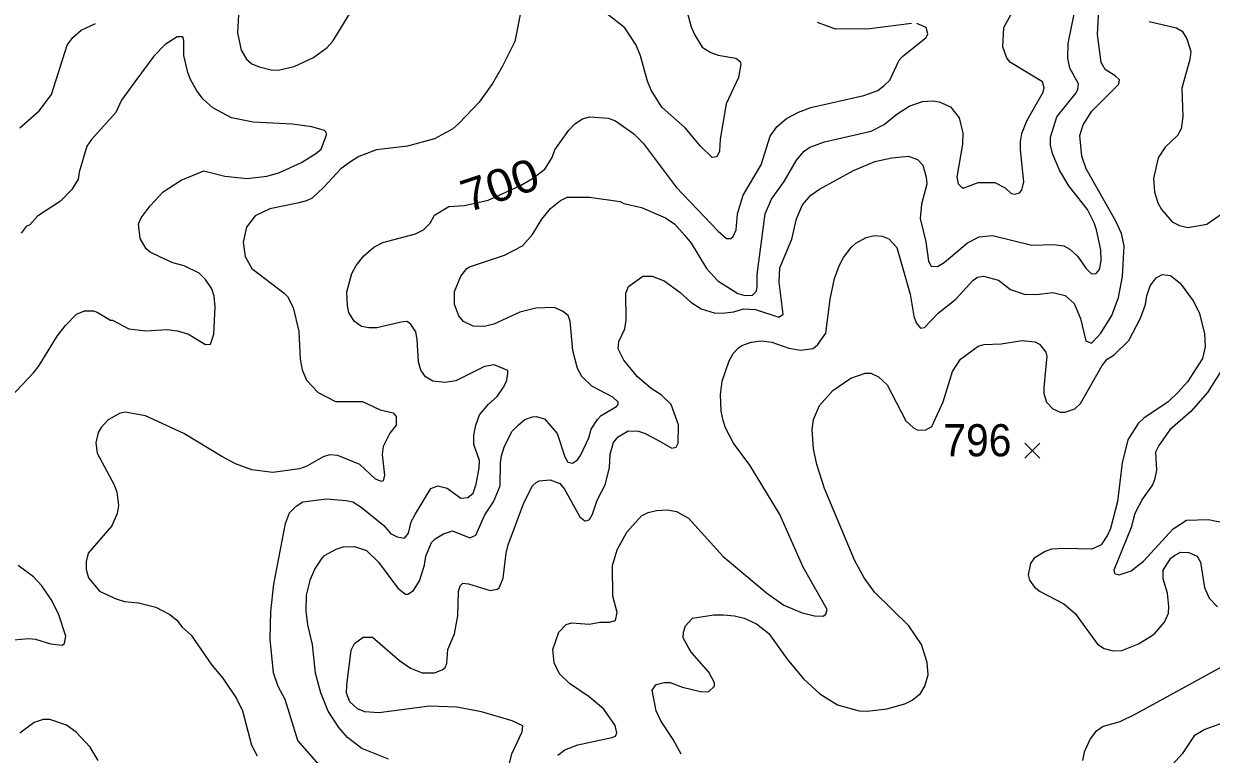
# Model space of a CAD drawing. Extents: x 294.2 to 320.3, y 7482.7 to 7510.7.
# Drawn here: x 304.291 to 307.247, y 7501.322 to 7503.14 of the extents above; entities that cross this region are included whole.
import ezdxf
from ezdxf.enums import TextEntityAlignment as Align

# ---------------------------------------------------------------- set-up
doc = ezdxf.new("R2010")
doc.units = 0
doc.header["$LTSCALE"] = 0.032
for name, color, linetype, lineweight in [('1', 7, 'Continuous', 25), ('2', 7, 'Continuous', 13), ('21', 7, 'Continuous', 25)]:
    doc.layers.add(name, color=color, linetype=linetype, lineweight=lineweight)
doc.layers.add('61', color=7, linetype='Continuous')

msp = doc.modelspace()

# ---------------------------------------------------------------- linework, layer by layer
at = {"layer": '1'}
for points in [[(305.1008, 7502.4213), (305.0969, 7502.4379), (305.0957, 7502.4724), (305.1083, 7502.5186), (305.1189, 7502.5383), (305.1377, 7502.5619), (305.1629, 7502.5839), (305.1849, 7502.5957), (305.2662, 7502.6169), (305.2866, 7502.6271), (305.3031, 7502.6436), (305.3136, 7502.6633), (305.3495, 7502.6853), (305.3883, 7502.6877), (305.4473, 7502.701), (305.5273, 7502.7372), (305.5572, 7502.7551), (305.5878, 7502.7779), (305.6063, 7502.807), (305.6134, 7502.8258), (305.648, 7502.8754), (305.6629, 7502.8911), (305.6818, 7502.9029), (305.6998, 7502.9084), (305.7459, 7502.9052), (305.7639, 7502.8981), (305.8095, 7502.8659), (305.8331, 7502.8423), (305.915, 7502.7332), (306.0195, 7502.6239), (306.0406, 7502.6051), (306.0508, 7502.6058), (306.0566, 7502.6102), (306.0642, 7502.6268), (306.0674, 7502.6664), (306.0821, 7502.713), (306.1262, 7502.7887), (306.149, 7502.8603), (306.1659, 7502.8831), (306.1895, 7502.9043), (306.2193, 7502.9201), (306.25, 7502.9311), (306.3819, 7502.961), (306.4173, 7502.9736), (306.4323, 7502.9862), (306.4464, 7502.9995), (306.47, 7503.0491), (306.4781, 7503.0585), (306.5373, 7503.1056), (306.5412, 7503.115), (306.5373, 7503.1308), (306.5141, 7503.1402)], [(306.5007, 7503.1402), (306.3973, 7503.1268), (306.3116, 7503.126), (306.2664, 7503.1433)], [(305.2448, 7502.3985), (305.2303, 7502.3969), (305.1705, 7502.3828), (305.1501, 7502.3828), (305.132, 7502.3867), (305.1139, 7502.3993), (305.1008, 7502.4213)], [(305.0269, 7501.2959), (304.9738, 7501.3564), (304.9424, 7501.4579), (304.9246, 7501.4904), (304.9131, 7501.5249), (304.9046, 7501.6084), (304.906, 7501.6768), (304.9142, 7501.745), (304.9429, 7501.896), (304.9531, 7501.9228), (304.9696, 7501.9393), (304.9861, 7501.9503), (305.0451, 7501.9574), (305.0942, 7501.9534), (305.1107, 7501.9503), (305.1312, 7501.9369), (305.1874, 7501.8913), (305.2039, 7501.8716), (305.2204, 7501.863), (305.2392, 7501.8599), (305.2487, 7501.8724), (305.2558, 7501.9), (305.266, 7501.9204), (305.3049, 7501.9833), (305.3222, 7501.9896), (305.345, 7501.9841), (305.3788, 7501.9589), (305.3969, 7501.9605), (305.4095, 7501.9715), (305.4173, 7501.9943), (305.4248, 7502.0336), (305.4256, 7502.0533), (305.4114, 7502.0926), (305.4114, 7502.1162), (305.4169, 7502.1413), (305.4258, 7502.1665), (305.4478, 7502.1932), (305.4698, 7502.2121), (305.4855, 7502.2357), (305.4926, 7502.2498), (305.4965, 7502.2687), (305.4958, 7502.2766), (305.4619, 7502.2907), (305.4384, 7502.2868), (305.367, 7502.2515), (305.3395, 7502.2467), (305.3096, 7502.2507), (305.2916, 7502.2609), (305.28, 7502.2774), (305.2737, 7502.2987), (305.2708, 7502.3544), (305.2669, 7502.3733), (305.2543, 7502.393), (305.2448, 7502.3985)]]:
    msp.add_lwpolyline(points, dxfattribs=at)
at = {"layer": '2'}
for points in [[(305.9302, 7503.2155), (305.9523, 7503.132), (305.9609, 7503.113), (305.9798, 7503.0819), (306.001, 7503.068), (306.0195, 7503.0617), (306.0636, 7503.054), (306.0745, 7503.0457), (306.0763, 7503.0393), (306.07, 7503.0061), (306.0393, 7502.9403), (306.0247, 7502.8529), (306.0227, 7502.8228), (306.0163, 7502.8088), (306.0049, 7502.8069), (305.9755, 7502.835), (305.9372, 7502.8809), (305.8803, 7502.9314), (305.8733, 7502.941), (305.8529, 7502.9742), (305.8433, 7502.9972), (305.8261, 7503.0597), (305.8152, 7503.0866), (305.7871, 7503.13), (305.7373, 7503.1689)], [(304.8262, 7503.1619), (304.8236, 7503.1172), (304.8326, 7503.0738), (304.846, 7503.0514), (304.8594, 7503.04), (304.8773, 7503.0329), (304.9073, 7503.0252), (304.9246, 7503.0246), (304.9641, 7503.0336), (305.0127, 7503.0559), (305.0465, 7503.0808), (305.0605, 7503.0967), (305.1161, 7503.1868)], [(305.5305, 7503.1798), (305.5132, 7503.0955), (305.4832, 7503.0342), (305.4577, 7502.9908), (305.4251, 7502.9448), (305.3753, 7502.8924), (305.3594, 7502.8784), (305.3134, 7502.8535), (305.2464, 7502.8356), (305.1697, 7502.826), (305.125, 7502.8094), (305.1046, 7502.796), (305.0803, 7502.7788), (305.0382, 7502.7328), (305.0088, 7502.706), (304.9954, 7502.699), (304.9731, 7502.6932), (304.9041, 7502.6792), (304.8676, 7502.6617), (304.846, 7502.6339), (304.8377, 7502.5962), (304.8428, 7502.5605), (304.8594, 7502.5311), (304.9392, 7502.4691), (304.9475, 7502.4608), (304.9622, 7502.434), (304.9756, 7502.374), (304.9794, 7502.3051), (304.9845, 7502.2783)], [(305.7753, 7502.6972), (305.785, 7502.6922), (305.8286, 7502.6824), (305.8887, 7502.6569), (305.9116, 7502.6415), (305.9365, 7502.6128), (305.9525, 7502.5936), (305.9902, 7502.5304), (306.0189, 7502.5004), (306.0687, 7502.4685), (306.0859, 7502.4634), (306.1051, 7502.464), (306.1146, 7502.4743), (306.1166, 7502.4851), (306.1166, 7502.5158), (306.1364, 7502.6664), (306.1523, 7502.7035), (306.1836, 7502.7475), (306.2143, 7502.8005), (306.2334, 7502.8228), (306.2475, 7502.8324), (306.2845, 7502.8459), (306.4007, 7502.8727), (306.4326, 7502.8893), (306.4639, 7502.9148), (306.4945, 7502.9346), (306.5284, 7502.9467), (306.5527, 7502.948), (306.5699, 7502.9455), (306.5976, 7502.9332), (306.6189, 7502.9059), (306.6286, 7502.8675), (306.628, 7502.8401), (306.6139, 7502.7584), (306.6172, 7502.7411), (306.6267, 7502.7315), (306.6318, 7502.7315), (306.6663, 7502.745), (306.7077, 7502.745), (306.7341, 7502.7316), (306.749, 7502.7177), (306.7582, 7502.716), (306.7691, 7502.7193), (306.7749, 7502.7255), (306.7801, 7502.7466), (306.7723, 7502.8261), (306.7717, 7502.8465), (306.7755, 7502.8669), (306.7876, 7502.8982), (306.8285, 7502.9697), (306.8308, 7502.9806), (306.8263, 7502.9951), (306.7468, 7503.0431), (306.7378, 7503.054), (306.7283, 7503.0827), (306.7308, 7503.1306), (306.7614, 7503.1862)], [(306.0585, 7502.4232), (306.0826, 7502.4307), (306.1125, 7502.4285), (306.1705, 7502.4096), (306.1811, 7502.4174), (306.1715, 7502.4966), (306.1728, 7502.5324), (306.2028, 7502.6039), (306.2149, 7502.6543), (306.2296, 7502.6894), (306.25, 7502.7131), (306.2717, 7502.7284), (306.356, 7502.7749), (306.4096, 7502.7967), (306.4518, 7502.8063), (306.4933, 7502.8101), (306.5156, 7502.8024), (306.529, 7502.7878), (306.5373, 7502.7584), (306.5386, 7502.7405), (306.5258, 7502.6907), (306.522, 7502.655), (306.536, 7502.5975), (306.5431, 7502.549), (306.5495, 7502.5362), (306.5654, 7502.5356), (306.582, 7502.5458), (306.6401, 7502.5943), (306.6689, 7502.6096), (306.7021, 7502.6128), (306.8004, 7502.5885), (306.8541, 7502.5906), (306.8794, 7502.5873), (306.8949, 7502.5789), (306.915, 7502.5606), (306.9345, 7502.5317), (306.9485, 7502.5177), (306.96, 7502.5183), (306.9683, 7502.5285), (306.9728, 7502.5502), (306.9722, 7502.5771), (306.9613, 7502.6269), (306.9555, 7502.6447), (306.9383, 7502.6779), (306.8923, 7502.7366), (306.8693, 7502.7756), (306.8514, 7502.8171), (306.8463, 7502.8376), (306.847, 7502.858), (306.8623, 7502.9078), (306.9102, 7502.9678), (306.9147, 7502.9773), (306.916, 7502.9901), (306.8949, 7503.0291), (306.8898, 7503.0546), (306.8904, 7503.091), (306.9076, 7503.176)], [(306.9721, 7502.3696), (306.9996, 7502.4142), (307.0156, 7502.4583), (307.0258, 7502.5107), (307.0296, 7502.5873), (307.0232, 7502.6179), (307.0092, 7502.6486), (306.9357, 7502.7788), (306.9242, 7502.8107), (306.9198, 7502.8618), (306.9281, 7502.8886), (306.9491, 7502.9225), (307.0168, 7502.9895), (307.0181, 7503.0003), (307.0073, 7503.0099), (306.983, 7503.0259), (306.9728, 7503.0432), (306.9638, 7503.1134), (306.9677, 7503.1894)], [(307.0922, 7503.1453), (307.1605, 7503.1293), (307.1739, 7503.1217), (307.186, 7503.1019), (307.1962, 7503.0712), (307.1937, 7503.0508), (307.1732, 7502.9793), (307.1758, 7502.9078), (307.1714, 7502.8784), (307.1624, 7502.8618), (307.1318, 7502.8324), (307.1145, 7502.8062), (307.103, 7502.7546), (307.1056, 7502.7214), (307.1139, 7502.6945), (307.1228, 7502.6779), (307.1496, 7502.6466), (307.1675, 7502.6377), (307.1886, 7502.6332), (307.2358, 7502.6409), (307.2735, 7502.6677)], [(304.2816, 7502.881), (304.3295, 7502.9231), (304.3601, 7502.9639), (304.3991, 7503.0866), (304.4137, 7503.1057), (304.4342, 7503.1236), (304.47, 7503.1402)], [(304.2446, 7502.1953), (304.3161, 7502.2712), (304.3301, 7502.2897), (304.3742, 7502.3625), (304.3953, 7502.3887), (304.4227, 7502.4168), (304.4425, 7502.4257), (304.4649, 7502.4251), (304.4738, 7502.4219), (304.507, 7502.4021), (304.5121, 7502.4021), (304.553, 7502.3804), (304.5951, 7502.3759), (304.6487, 7502.3791), (304.6743, 7502.3753), (304.7011, 7502.3676), (304.7438, 7502.3415), (304.756, 7502.3427), (304.7643, 7502.3676), (304.7681, 7502.4353), (304.7656, 7502.4621), (304.7592, 7502.48), (304.7439, 7502.503), (304.7279, 7502.5189), (304.6909, 7502.5374), (304.6621, 7502.5445), (304.6321, 7502.5591), (304.6059, 7502.5713), (304.5964, 7502.5796), (304.581, 7502.6052), (304.5772, 7502.6422), (304.5836, 7502.6568), (304.606, 7502.6869), (304.6381, 7502.7215), (304.6835, 7502.751), (304.7398, 7502.7736), (304.792, 7502.7608), (304.8472, 7502.7544), (304.896, 7502.7605), (304.9264, 7502.7688), (304.9827, 7502.7942), (305.0183, 7502.817), (305.0315, 7502.8276), (305.0452, 7502.8632), (305.0441, 7502.8702), (305.0395, 7502.8746), (305.0085, 7502.883), (304.9602, 7502.8896), (304.8621, 7502.8949), (304.8087, 7502.9058), (304.7622, 7502.9308), (304.7381, 7502.9518), (304.7222, 7502.9729), (304.7062, 7503.001), (304.6998, 7503.0189), (304.6896, 7503.061), (304.6902, 7503.0981), (304.687, 7503.107), (304.6736, 7503.107), (304.6436, 7503.0885), (304.6155, 7503.0591), (304.5676, 7502.9952), (304.5351, 7502.9493), (304.521, 7502.9193), (304.4604, 7502.8522), (304.4482, 7502.8348), (304.4293, 7502.7707), (304.427, 7502.7529), (304.4115, 7502.727), (304.3828, 7502.6981), (304.3254, 7502.6608), (304.3065, 7502.6394), (304.2973, 7502.6349), (304.2848, 7502.6185)], [(305.5579, 7502.6154), (305.5809, 7502.6537), (305.602, 7502.6798), (305.6269, 7502.6996), (305.6435, 7502.7079), (305.6997, 7502.7079), (305.7753, 7502.6972)], [(305.1991, 7501.3097), (305.1327, 7501.3365), (305.0969, 7501.3633), (305.0752, 7501.3882), (305.0491, 7501.4291), (305.0305, 7501.4751), (305.0177, 7501.5236), (305.0101, 7501.5951), (304.9986, 7501.6436), (304.9941, 7501.6781), (304.9947, 7501.7177), (305.005, 7501.7573), (305.0159, 7501.7828), (305.0337, 7501.8096), (305.0401, 7501.8166), (305.0689, 7501.8326), (305.0867, 7501.8383), (305.1148, 7501.8392), (305.1441, 7501.8292), (305.1739, 7501.8002), (305.2227, 7501.7356), (305.2412, 7501.7202), (305.2476, 7501.7202), (305.2617, 7501.7294), (305.2766, 7501.7539), (305.2887, 7501.7929), (305.2922, 7501.8146), (305.306, 7501.8489), (305.3151, 7501.8584), (305.3364, 7501.8706), (305.3582, 7501.8779), (305.4013, 7501.8606), (305.4162, 7501.867), (305.4386, 7501.9177), (305.4604, 7501.95), (305.4771, 7501.9898), (305.4782, 7502.0471), (305.48, 7502.0647), (305.4869, 7502.0858), (305.5064, 7502.1253), (305.5225, 7502.1415), (305.5388, 7502.155), (305.5579, 7502.162), (305.5669, 7502.1627), (305.5873, 7502.1563), (305.6192, 7502.1199), (305.6377, 7502.0625), (305.6454, 7502.049), (305.6569, 7502.0465), (305.6694, 7502.0545), (305.6769, 7502.0656), (305.6976, 7502.1091), (305.7033, 7502.1308), (305.7189, 7502.1549), (305.7281, 7502.1649), (305.7666, 7502.1872), (305.7706, 7502.1922), (305.7706, 7502.1983), (305.7574, 7502.2106), (305.7054, 7502.238), (305.6805, 7502.2623), (305.6697, 7502.2821), (305.6575, 7502.3268), (305.6511, 7502.3996), (305.646, 7502.4136), (305.632, 7502.4245), (305.6115, 7502.4334), (305.5656, 7502.4321), (305.526, 7502.4225), (305.4609, 7502.3925), (305.4379, 7502.3862), (305.4096, 7502.387), (305.3854, 7502.3992), (305.374, 7502.4126), (305.3636, 7502.441), (305.3632, 7502.4736), (305.3791, 7502.5119), (305.3938, 7502.5304), (305.4008, 7502.5349), (305.4877, 7502.5636), (305.5324, 7502.5872), (305.5579, 7502.6154)], [(305.6205, 7501.3199), (305.6377, 7501.3333), (305.6703, 7501.3454), (305.7546, 7501.3633), (305.7642, 7501.3671), (305.7673, 7501.3755), (305.7635, 7501.3933), (305.7354, 7501.4342), (305.6984, 7501.4648), (305.6498, 7501.498), (305.625, 7501.5223), (305.6115, 7501.5491), (305.6084, 7501.5823), (305.623, 7501.6257), (305.6409, 7501.6449), (305.655, 7501.6487), (305.6984, 7501.6455), (305.7252, 7501.6506), (305.7495, 7501.6506), (305.7641, 7501.6551), (305.768, 7501.6743), (305.7578, 7501.7151), (305.7565, 7501.7917), (305.768, 7501.8307), (305.7922, 7501.8747), (305.8286, 7501.915), (305.8452, 7501.9239), (305.8663, 7501.9283), (305.8938, 7501.9303), (305.9155, 7501.9264), (305.9461, 7501.9092), (306.0323, 7501.8141), (306.1402, 7501.724), (306.183, 7501.6928), (306.2283, 7501.6736), (306.259, 7501.6665), (306.2807, 7501.6659), (306.2877, 7501.6704), (306.2909, 7501.6825), (306.2315, 7501.7879), (306.1734, 7501.9182), (306.1281, 7501.9922), (306.0981, 7502.0414), (306.0579, 7502.0957), (306.038, 7502.134), (306.0323, 7502.1524), (306.0272, 7502.1761), (306.0253, 7502.217), (306.0298, 7502.2502), (306.047, 7502.3012), (306.0572, 7502.3191), (306.0699, 7502.3331), (306.0783, 7502.3395), (306.1019, 7502.3478), (306.1275, 7502.351), (306.153, 7502.3472), (306.1951, 7502.3325), (306.2245, 7502.3274), (306.2558, 7502.3319), (306.2679, 7502.3415), (306.2877, 7502.3702), (306.2979, 7502.4545), (306.3087, 7502.5056), (306.3209, 7502.5375), (306.3311, 7502.5579), (306.3509, 7502.5828), (306.3624, 7502.5936), (306.388, 7502.6077), (306.4084, 7502.6128), (306.4275, 7502.6115), (306.4441, 7502.6045), (306.4639, 7502.5834), (306.4977, 7502.4672), (306.5067, 7502.4123), (306.5124, 7502.3957), (306.5227, 7502.3823), (306.5329, 7502.3836), (306.5667, 7502.4194), (306.6112, 7502.4545), (306.6534, 7502.5013), (306.6651, 7502.5094), (306.6797, 7502.5113), (306.7174, 7502.5017), (306.7474, 7502.4787), (306.7813, 7502.4666), (306.8119, 7502.4659), (306.8528, 7502.471), (306.8834, 7502.4634)], [(305.4947, 7501.2758), (305.5062, 7501.3231), (305.5317, 7501.378), (305.5336, 7501.3927), (305.5069, 7501.4055), (305.4302, 7501.4272), (305.3689, 7501.4393), (305.3013, 7501.4412), (305.1755, 7501.4252), (305.1406, 7501.4276), (305.1222, 7501.4349), (305.1033, 7501.4521), (305.095, 7501.4738), (305.0956, 7501.4942), (305.1065, 7501.581), (305.1148, 7501.5976), (305.1359, 7501.6136), (305.1595, 7501.6136), (305.2265, 7501.5549), (305.254, 7501.5363), (305.2827, 7501.5242), (305.314, 7501.5242), (305.3325, 7501.5318), (305.3402, 7501.5382), (305.3447, 7501.5478), (305.3466, 7501.5829), (305.3638, 7501.6219), (305.3715, 7501.6666), (305.3734, 7501.7266), (305.3779, 7501.7413), (305.3843, 7501.7477), (305.3983, 7501.7464), (305.4519, 7501.7291), (305.4698, 7501.7324), (305.4743, 7501.7362), (305.4845, 7501.7604), (305.4922, 7501.8224), (305.4966, 7501.8428), (305.5362, 7501.9475), (305.5573, 7501.9903), (305.5668, 7501.9986), (305.5745, 7502.0024), (305.6013, 7502.0049), (305.6256, 7501.9954), (305.6371, 7501.982), (305.6754, 7501.913), (305.6875, 7501.9028), (305.6933, 7501.9035), (305.699, 7501.906), (305.7067, 7501.9194), (305.7182, 7501.9539), (305.7386, 7501.9922), (305.7488, 7502.0344), (305.7507, 7502.0688), (305.759, 7502.0975), (305.7705, 7502.1122), (305.7954, 7502.1269), (305.821, 7502.1257), (305.8363, 7502.1211), (305.8708, 7502.1027), (305.904, 7502.0835), (305.9148, 7502.0861), (305.9199, 7502.0957), (305.921, 7502.1419), (305.9027, 7502.192), (305.8778, 7502.2163), (305.8529, 7502.2322), (305.8184, 7502.261), (305.7846, 7502.3025), (305.7711, 7502.3312), (305.7724, 7502.3491), (305.7877, 7502.3804), (305.7903, 7502.4021), (305.7897, 7502.469), (305.7966, 7502.4863), (305.8322, 7502.5113), (305.8552, 7502.5119), (305.8855, 7502.5004)], [(305.8855, 7502.5004), (305.9242, 7502.472), (305.9518, 7502.4472), (305.9776, 7502.4305), (306.0097, 7502.4205), (306.0293, 7502.4193), (306.0585, 7502.4232)], [(307.0864, 7502.4629), (307.095, 7502.4873), (307.1092, 7502.5078), (307.1241, 7502.5156), (307.1449, 7502.5132), (307.1693, 7502.4944), (307.2015, 7502.4503), (307.2165, 7502.4212), (307.2299, 7502.3693), (307.2319, 7502.3355), (307.2248, 7502.3072), (307.1874, 7502.2487), (307.1646, 7502.2227), (307.1394, 7502.1992), (307.0787, 7502.1583), (307.0645, 7502.1449), (307.0393, 7502.104), (307.0251, 7502.0471), (307.013, 7501.9507), (306.9957, 7501.8837), (306.9888, 7501.8671), (306.9728, 7501.8428), (306.9498, 7501.8326), (306.8796, 7501.8338), (306.8489, 7501.832), (306.8336, 7501.8268), (306.8061, 7501.8102), (306.7972, 7501.7968), (306.7914, 7501.7687), (306.7947, 7501.7553), (306.8068, 7501.7381), (306.8208, 7501.7266), (306.8795, 7501.6966), (306.9083, 7501.6723), (306.9632, 7501.5957), (306.9804, 7501.5848), (307.0022, 7501.5791), (307.0239, 7501.5804), (307.0653, 7501.597), (307.0916, 7501.6123), (307.1056, 7501.6219), (307.1305, 7501.6506), (307.14, 7501.673), (307.1407, 7501.6896), (307.1375, 7501.7228), (307.1267, 7501.7585), (307.1267, 7501.7802), (307.1458, 7501.8096), (307.1554, 7501.8166), (307.1701, 7501.8249), (307.1912, 7501.8243), (307.2116, 7501.8147), (307.2199, 7501.8), (307.2301, 7501.7368), (307.2416, 7501.7106), (307.262, 7501.6889)], [(306.8834, 7502.4634), (306.9057, 7502.4436), (306.9211, 7502.406), (306.9345, 7502.3504), (306.9485, 7502.3453), (306.9645, 7502.3619), (306.9721, 7502.3696)], [(306.9749, 7502.2896), (306.9874, 7502.3053), (307.0051, 7502.3159), (307.0418, 7502.3513), (307.0707, 7502.4071), (307.0832, 7502.4409), (307.0864, 7502.4629)], [(305.9276, 7501.3218), (305.9072, 7501.3588), (305.8765, 7501.4048), (305.865, 7501.4304), (305.8554, 7501.4814), (305.8656, 7501.4955), (305.8848, 7501.5005), (305.9001, 7501.5006), (305.9308, 7501.4885), (305.9793, 7501.477), (305.9965, 7501.4782), (306.0106, 7501.491), (306.0106, 7501.4993), (305.9965, 7501.5261), (305.9531, 7501.5753), (305.9468, 7501.5861), (305.9327, 7501.6117), (305.9333, 7501.6257), (305.9384, 7501.6417), (305.9557, 7501.6608), (306.0087, 7501.6691), (306.033, 7501.6691), (306.0598, 7501.6666), (306.084, 7501.6602), (306.1147, 7501.6468), (306.1453, 7501.6225), (306.1913, 7501.5587), (306.2321, 7501.5095), (306.2724, 7501.4725), (306.3164, 7501.445), (306.3701, 7501.4297), (306.3905, 7501.4291), (306.4396, 7501.4348), (306.4837, 7501.4476), (306.5022, 7501.4565), (306.5233, 7501.4731), (306.5342, 7501.4917), (306.5418, 7501.5197), (306.5399, 7501.5504), (306.5252, 7501.5951), (306.494, 7501.6419), (306.409, 7501.7251), (306.3828, 7501.7611), (306.3598, 7501.8032), (306.2844, 7501.9834), (306.2653, 7502.0432), (306.2566, 7502.0817), (306.2538, 7502.1301), (306.2571, 7502.155), (306.2717, 7502.1895), (306.3049, 7502.2271), (306.3496, 7502.2578), (306.3854, 7502.2699), (306.3994, 7502.2699), (306.4186, 7502.261), (306.4403, 7502.2412), (306.4869, 7502.1518), (306.5054, 7502.1339), (306.515, 7502.1295), (306.5348, 7502.1282), (306.5514, 7502.1378), (306.5795, 7502.1991), (306.6031, 7502.2744), (306.6229, 7502.305), (306.6663, 7502.3376), (306.6817, 7502.3415), (306.7238, 7502.3433), (306.7761, 7502.3517), (306.8087, 7502.3485), (306.8196, 7502.3421), (306.8349, 7502.3229), (306.8374, 7502.3127), (306.8297, 7502.2348), (306.8297, 7502.2195), (306.8368, 7502.1978), (306.8521, 7502.1818), (306.8706, 7502.1729), (306.8834, 7502.1729), (306.9075, 7502.1819), (306.9216, 7502.1952), (306.9749, 7502.2896)], [(304.9845, 7502.2783), (304.9954, 7502.2527), (305.0242, 7502.222), (305.0676, 7502.1997), (305.1346, 7502.1995), (305.1787, 7502.1793), (305.211, 7502.1716)], [(307.2716, 7502.2757), (307.2377, 7502.2219), (307.1956, 7502.1748), (307.1432, 7502.1289), (307.1158, 7502.0905), (307.1081, 7502.0733), (307.1101, 7502.0293), (307.1056, 7502.005), (307.1005, 7501.9922), (307.0756, 7501.9577), (307.0564, 7501.9207), (307.0475, 7501.8862), (307.0041, 7501.7802), (307.006, 7501.7719), (307.0175, 7501.7681), (307.0475, 7501.7783), (307.0781, 7501.8026), (307.1515, 7501.883), (307.1854, 7501.9041), (307.2397, 7501.906), (307.3035, 7501.8927)], [(305.211, 7502.1716), (305.2185, 7502.1621), (305.2185, 7502.1409), (305.2024, 7502.1214), (305.1857, 7502.088), (305.1837, 7502.0676), (305.1888, 7502.0165), (305.1857, 7502.0024), (305.1818, 7502.0005), (305.1665, 7502.0062), (305.1276, 7502.0427), (305.0727, 7502.065), (305.0523, 7502.0669), (305.0363, 7502.0624), (304.9961, 7502.0388), (304.9778, 7502.0323), (304.9117, 7502.0229), (304.8594, 7502.0299), (304.8186, 7502.0445), (304.7841, 7502.0631), (304.6896, 7502.1205), (304.5945, 7502.164), (304.544, 7502.1735), (304.53, 7502.1703), (304.5012, 7502.1543), (304.484, 7502.1352), (304.477, 7502.1225), (304.4706, 7502.0969), (304.4744, 7502.0714), (304.5166, 7501.9922), (304.523, 7501.9743), (304.5274, 7501.9411), (304.5242, 7501.9207), (304.5108, 7501.8901), (304.452, 7501.8224), (304.4469, 7501.802), (304.4469, 7501.7815), (304.4527, 7501.7611), (304.4797, 7501.7275), (304.5217, 7501.7085), (304.5423, 7501.7019), (304.5774, 7501.6985), (304.6199, 7501.6877), (304.6549, 7501.6699), (304.6721, 7501.6554), (304.6859, 7501.6381), (304.7077, 7501.6184), (304.7592, 7501.544), (304.7866, 7501.5114), (304.8211, 7501.4604), (304.8358, 7501.4304), (304.8581, 7501.3448), (304.8722, 7501.318)], [(304.3365, 7501.7407), (304.3161, 7501.7636), (304.2778, 7501.7917)], [(304.3576, 7501.597), (304.3869, 7501.5938), (304.3927, 7501.5976), (304.3965, 7501.6155), (304.3787, 7501.6691), (304.3614, 7501.7049), (304.3365, 7501.7407)], [(304.2465, 7501.6047), (304.304, 7501.6104), (304.3206, 7501.6085), (304.3576, 7501.597)], [(307.4452, 7501.2656), (307.4497, 7501.3244), (307.458, 7501.3588), (307.495, 7501.4585), (307.504, 7501.4917), (307.5065, 7501.5172), (307.4989, 7501.5491), (307.4906, 7501.5644), (307.4695, 7501.5823), (307.4542, 7501.5861), (307.4133, 7501.5881), (307.3967, 7501.5842), (307.2946, 7501.5484), (307.2652, 7501.535), (307.0584, 7501.4214), (307.0188, 7501.4029), (306.9779, 7501.3914), (306.9587, 7501.3774), (306.9453, 7501.3601), (306.93, 7501.3269), (306.9262, 7501.3065)], [(307.3686, 7501.2937), (307.3712, 7501.341), (307.3712, 7501.3767), (307.3603, 7501.4284), (307.352, 7501.4367), (307.3399, 7501.4342), (307.3227, 7501.4195), (307.3061, 7501.4106), (307.2307, 7501.3837), (307.2039, 7501.3678), (307.1739, 7501.3231), (307.1267, 7501.2707)], [(304.4763, 7501.3065), (304.4566, 7501.3397), (304.4217, 7501.3773), (304.3976, 7501.394), (304.3562, 7501.4085), (304.3401, 7501.4085), (304.3177, 7501.4007), (304.2816, 7501.3741)]]:
    msp.add_lwpolyline(points, dxfattribs=at)
at = {"layer": '21'}
for p, q in [((306.7828, 7502.096), (306.8203, 7502.0585)), ((306.8203, 7502.096), (306.7828, 7502.0585))]:
    msp.add_line(p, q, dxfattribs=at)

# ---------------------------------------------------------------- texts
at = {"layer": '61', "width": 1.1}
msp.add_text('700', height=0.08, rotation=18.46, dxfattribs=at).set_placement((305.4887, 7502.7008), align=Align.CENTER)
at = {"layer": '61', "width": 0.95}
msp.add_text('796', height=0.08, dxfattribs=at).set_placement((306.6646, 7502.0634), align=Align.CENTER)

doc.saveas('drawing.dxf')
